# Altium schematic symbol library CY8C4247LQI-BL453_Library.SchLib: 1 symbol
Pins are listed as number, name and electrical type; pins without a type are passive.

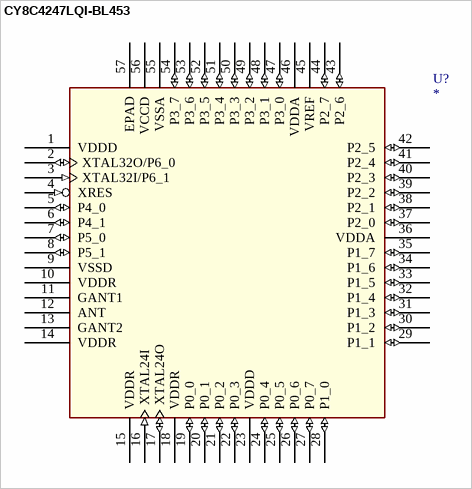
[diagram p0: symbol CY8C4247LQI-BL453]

## CY8C4247LQI-BL453
designator U?
footprint TBD
pins: 1 VDDD (power), 2 XTAL32O/P6_0 (io), 3 XTAL32I/P6_1 (in), 4 XRES (in), 5 P4_0 (io), 6 P4_1 (io), 7 P5_0 (io), 8 P5_1 (io), 9 VSSD (power), 10 VDDR (power), 11 GANT1 (power), 12 ANT, 13 GANT2 (power), 14 VDDR (power), 15 VDDR (power), 16 XTAL24I (in), 17 XTAL24O (io), 18 VDDR (power), 19 P0_0 (io), 20 P0_1 (io), 21 P0_2 (io), 22 P0_3 (io), 23 VDDD (power), 24 P0_4 (io), 25 P0_5 (io), 26 P0_6 (io), 27 P0_7 (io), 28 P1_0 (io), 29 P1_1 (io), 30 P1_2 (io), 31 P1_3 (io), 32 P1_4 (io), 33 P1_5 (io), 34 P1_6 (io), 35 P1_7 (io), 36 VDDA (power), 37 P2_0 (io), 38 P2_1 (io), 39 P2_2 (io), 40 P2_3 (io), 41 P2_4 (io), 42 P2_5 (io), 43 P2_6 (io), 44 P2_7 (io), 45 VREF (power), 46 VDDA (power), 47 P3_0 (io), 48 P3_1 (io), 49 P3_2 (io), 50 P3_3 (io), 51 P3_4 (io), 52 P3_5 (io), 53 P3_6 (io), 54 P3_7 (io), 55 VSSA (power), 56 VCCD (power), 57 EPAD (power)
